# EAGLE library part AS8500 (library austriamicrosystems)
Universal multi pupose data aquisition system Source: AS8500_rev1_2_22-12-06.pdf
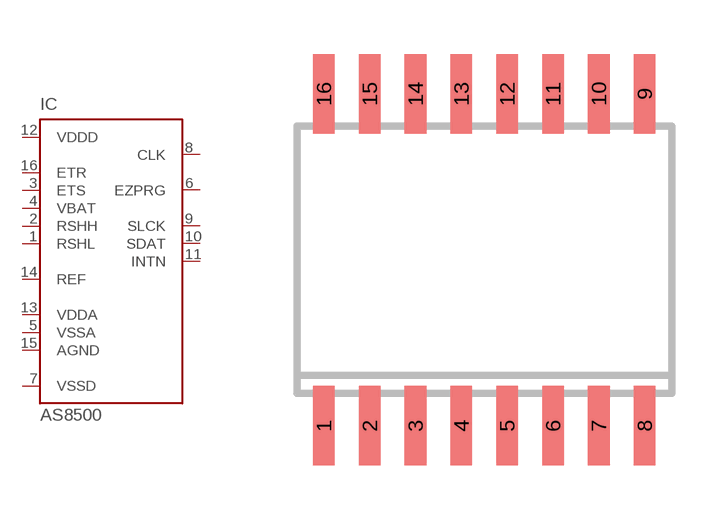
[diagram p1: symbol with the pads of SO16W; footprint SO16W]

Designator prefix IC

## AS8500 (MPN: AS8500ASOT; OC_FARNELL: unknown; OC_NEWARK: 59P4095)  [SO16W]
1  RSHL  in
2  RSHH  in
3  ETS
4  VBAT
5  VSSA  pwr
6  EZPRG  in
7  VSSD  pwr
8  CLK  in
9  SLCK  in
10  SDAT
11  INTN
12  VDDD  pwr
13  VDDA  pwr
14  REF  pas
15  AGND  pwr
16  ETR

## Footprint SO16W (pad centres in mm)
SMALL OUTLINE INTEGRATED CIRCUIT wide body 7.5 mm/JEDEC MS-013AA
smd 0.6 x 2.2: 1 -4.445,-4.6; 2 -3.175,-4.6; 3 -1.905,-4.6; 4 -0.635,-4.6; 5 0.635,-4.6; 6 1.905,-4.6; 7 3.175,-4.6; 8 4.445,-4.6; 9 4.445,4.6; 10 3.175,4.6; 11 1.905,4.6; 12 0.635,4.6; 13 -0.635,4.6; 14 -1.905,4.6; 15 -3.175,4.6; 16 -4.445,4.6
